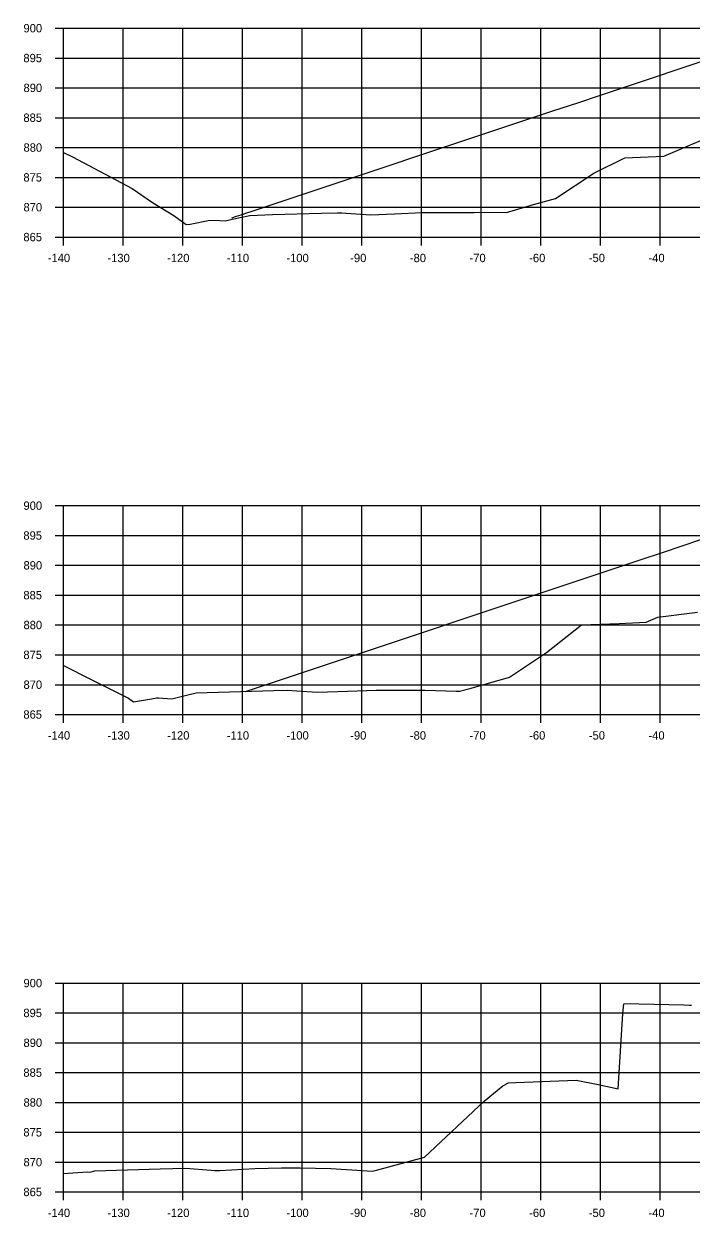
# Model space of a CAD drawing. Extents: x 1098669 to 1198896, y 698679 to 704410.
# Drawn here: x 1113352.2 to 1113464.1, y 701994.3 to 702194.3 of the extents above; entities that cross this region are included whole.
import ezdxf

# ---------------------------------------------------------------- set-up
doc = ezdxf.new("R2010")
doc.units = 0
for name, color, linetype in [('R_Alt Surface', 7, 'Continuous'), ('R_Axis', 7, 'Continuous'), ('R_Axis Annot', 7, 'Continuous'), ('R_Fin Surface', 7, 'Continuous'), ('R_Grid', 7, 'Continuous')]:
    doc.layers.add(name, color=color, linetype=linetype)

msp = doc.modelspace()

# ---------------------------------------------------------------- linework, layer by layer
at = {"layer": 'R_Alt Surface'}
for points in [[(1113358.87, 702172.72), (1113360.36, 702171.98), (1113370.35, 702166.7), (1113373.79, 702164.37), (1113377.36, 702162.16), (1113379.43, 702160.64), (1113380.09, 702160.75), (1113383.37, 702161.41), (1113385.07, 702161.33), (1113385.98, 702161.28), (1113387.14, 702161.57), (1113390.09, 702162.2), (1113393.86, 702162.32), (1113402.08, 702162.55), (1113404.77, 702162.63), (1113405.48, 702162.64), (1113406.2, 702162.59), (1113410.35, 702162.29), (1113414.32, 702162.44), (1113419, 702162.7), (1113422.09, 702162.69), (1113425.76, 702162.68), (1113427.67, 702162.68), (1113428.77, 702162.73), (1113433.12, 702162.68), (1113437.65, 702163.99), (1113441.3, 702165.02), (1113447.73, 702169.29), (1113452.93, 702171.81), (1113459.47, 702172.09), (1113465.81, 702174.79)], [(1113358.87, 702086.76), (1113363.51, 702084.43), (1113369.72, 702081.31), (1113370.59, 702080.67), (1113373.91, 702081.23), (1113374.46, 702081.34), (1113374.75, 702081.33), (1113377.03, 702081.21), (1113379.94, 702081.93), (1113381.06, 702082.17), (1113394.08, 702082.57), (1113396.35, 702082.63), (1113397.94, 702082.52), (1113401.35, 702082.3), (1113404.84, 702082.39), (1113411.26, 702082.66), (1113411.4, 702082.66), (1113419.49, 702082.62), (1113424.66, 702082.49), (1113425.22, 702082.45), (1113427.21, 702083), (1113433.62, 702084.8), (1113439.83, 702088.93), (1113445.7, 702093.57), (1113452.02, 702093.83), (1113456.54, 702094.02), (1113458.5, 702094.86), (1113465.11, 702095.69)], [(1113358.87, 702001.68), (1113362.84, 702001.94), (1113363.25, 702001.9), (1113364.08, 702002.1), (1113375.06, 702002.44), (1113379.29, 702002.57), (1113383.62, 702002.19), (1113384.18, 702002.13), (1113385.03, 702002.18), (1113390.92, 702002.48), (1113395.4, 702002.6), (1113398.51, 702002.59), (1113403.68, 702002.52), (1113408.93, 702002.14), (1113410.59, 702002.03), (1113411.34, 702002.23), (1113419.39, 702004.41), (1113429.36, 702013.77), (1113432.47, 702016.36), (1113433.42, 702016.83), (1113434.66, 702016.91), (1113444.78, 702017.28), (1113448.46, 702016.56), (1113451.84, 702015.83), (1113452.59, 702028.48), (1113452.8, 702030.1), (1113453.94, 702030.13), (1113455.28, 702030.1), (1113462.83, 702029.94), (1113463.79, 702029.84), (1113464.1, 702029.84)]]:
    msp.add_lwpolyline(points, dxfattribs=at)
at = {"layer": 'R_Axis'}
for p, q in [((1113357.47, 702193.56), (1113358.87, 702193.56)), ((1113358.87, 702158.56), (1113358.87, 702193.56)), ((1113357.47, 702188.56), (1113358.87, 702188.56)), ((1113357.47, 702183.56), (1113358.87, 702183.56)), ((1113357.47, 702178.56), (1113358.87, 702178.56)), ((1113357.47, 702173.56), (1113358.87, 702173.56)), ((1113357.47, 702168.56), (1113358.87, 702168.56)), ((1113357.47, 702163.56), (1113358.87, 702163.56)), ((1113357.47, 702158.56), (1113358.87, 702158.56)), ((1113358.87, 702158.56), (1113638.87, 702158.56)), ((1113358.87, 702157.16), (1113358.87, 702158.56)), ((1113368.87, 702157.16), (1113368.87, 702158.56)), ((1113378.87, 702157.16), (1113378.87, 702158.56)), ((1113388.87, 702157.16), (1113388.87, 702158.56)), ((1113398.87, 702157.16), (1113398.87, 702158.56)), ((1113408.87, 702157.16), (1113408.87, 702158.56)), ((1113418.87, 702157.16), (1113418.87, 702158.56)), ((1113428.87, 702157.16), (1113428.87, 702158.56)), ((1113438.87, 702157.16), (1113438.87, 702158.56)), ((1113448.87, 702157.16), (1113448.87, 702158.56)), ((1113458.87, 702157.16), (1113458.87, 702158.56)), ((1113357.47, 702113.56), (1113358.87, 702113.56)), ((1113358.87, 702078.56), (1113358.87, 702113.56)), ((1113357.47, 702108.56), (1113358.87, 702108.56)), ((1113357.47, 702103.56), (1113358.87, 702103.56)), ((1113357.47, 702098.56), (1113358.87, 702098.56)), ((1113357.47, 702093.56), (1113358.87, 702093.56)), ((1113357.47, 702088.56), (1113358.87, 702088.56)), ((1113357.47, 702083.56), (1113358.87, 702083.56)), ((1113357.47, 702078.56), (1113358.87, 702078.56)), ((1113358.87, 702078.56), (1113638.87, 702078.56)), ((1113358.87, 702077.16), (1113358.87, 702078.56)), ((1113368.87, 702077.16), (1113368.87, 702078.56)), ((1113378.87, 702077.16), (1113378.87, 702078.56)), ((1113388.87, 702077.16), (1113388.87, 702078.56)), ((1113398.87, 702077.16), (1113398.87, 702078.56)), ((1113408.87, 702077.16), (1113408.87, 702078.56)), ((1113418.87, 702077.16), (1113418.87, 702078.56)), ((1113428.87, 702077.16), (1113428.87, 702078.56)), ((1113438.87, 702077.16), (1113438.87, 702078.56)), ((1113448.87, 702077.16), (1113448.87, 702078.56)), ((1113458.87, 702077.16), (1113458.87, 702078.56)), ((1113357.47, 702033.56), (1113358.87, 702033.56)), ((1113358.87, 701998.56), (1113358.87, 702033.56)), ((1113357.47, 702028.56), (1113358.87, 702028.56)), ((1113357.47, 702023.56), (1113358.87, 702023.56)), ((1113357.47, 702018.56), (1113358.87, 702018.56)), ((1113357.47, 702013.56), (1113358.87, 702013.56)), ((1113357.47, 702008.56), (1113358.87, 702008.56)), ((1113357.47, 702003.56), (1113358.87, 702003.56)), ((1113357.47, 701998.56), (1113358.87, 701998.56)), ((1113358.87, 701998.56), (1113638.87, 701998.56)), ((1113358.87, 701997.16), (1113358.87, 701998.56)), ((1113368.87, 701997.16), (1113368.87, 701998.56)), ((1113378.87, 701997.16), (1113378.87, 701998.56)), ((1113388.87, 701997.16), (1113388.87, 701998.56)), ((1113398.87, 701997.16), (1113398.87, 701998.56)), ((1113408.87, 701997.16), (1113408.87, 701998.56)), ((1113418.87, 701997.16), (1113418.87, 701998.56)), ((1113428.87, 701997.16), (1113428.87, 701998.56)), ((1113438.87, 701997.16), (1113438.87, 701998.56)), ((1113448.87, 701997.16), (1113448.87, 701998.56)), ((1113458.87, 701997.16), (1113458.87, 701998.56))]:
    msp.add_line(p, q, dxfattribs=at)
at = {"layer": 'R_Fin Surface'}
for points in [[(1113387.06, 702161.77), (1113387.86, 702162.04), (1113388.65, 702162.3), (1113389.02, 702162.42), (1113389.27, 702162.5), (1113390.8, 702163), (1113440.89, 702179.69), (1113445.22, 702181.13), (1113448.51, 702182.23), (1113471.13, 702189.78)], [(1113389.33, 702082.42), (1113456.55, 702104.82), (1113458.27, 702105.39), (1113459.57, 702105.82), (1113468.51, 702108.81), (1113468.94, 702108.95), (1113469.65, 702109.19), (1113471.08, 702109.67), (1113475.37, 702111.1), (1113480.37, 702111), (1113483.37, 702110.94), (1113483.87, 702110.94), (1113484.87, 702110.46), (1113498.87, 702110.74), (1113512.87, 702110.46), (1113513.87, 702110.94), (1113514.37, 702110.94), (1113517.37, 702111), (1113522.37, 702111.1), (1113582.64, 702091.01), (1113598.79, 702096.4)]]:
    msp.add_lwpolyline(points, dxfattribs=at)
at = {"layer": 'R_Grid'}
for p, q in [((1113358.87, 702193.56), (1113638.87, 702193.56)), ((1113358.87, 702158.56), (1113358.87, 702193.56)), ((1113368.87, 702158.56), (1113368.87, 702193.56)), ((1113378.87, 702158.56), (1113378.87, 702193.56)), ((1113388.87, 702158.56), (1113388.87, 702193.56)), ((1113398.87, 702158.56), (1113398.87, 702193.56)), ((1113408.87, 702158.56), (1113408.87, 702193.56)), ((1113418.87, 702158.56), (1113418.87, 702193.56)), ((1113428.87, 702158.56), (1113428.87, 702193.56)), ((1113438.87, 702158.56), (1113438.87, 702193.56)), ((1113448.87, 702158.56), (1113448.87, 702193.56)), ((1113458.87, 702158.56), (1113458.87, 702193.56)), ((1113358.87, 702188.56), (1113638.87, 702188.56)), ((1113358.87, 702183.56), (1113638.87, 702183.56)), ((1113358.87, 702178.56), (1113638.87, 702178.56)), ((1113358.87, 702173.56), (1113638.87, 702173.56)), ((1113358.87, 702168.56), (1113638.87, 702168.56)), ((1113358.87, 702163.56), (1113638.87, 702163.56)), ((1113358.87, 702158.56), (1113638.87, 702158.56)), ((1113358.87, 702113.56), (1113638.87, 702113.56)), ((1113358.87, 702078.56), (1113358.87, 702113.56)), ((1113368.87, 702078.56), (1113368.87, 702113.56)), ((1113378.87, 702078.56), (1113378.87, 702113.56)), ((1113388.87, 702078.56), (1113388.87, 702113.56)), ((1113398.87, 702078.56), (1113398.87, 702113.56)), ((1113408.87, 702078.56), (1113408.87, 702113.56)), ((1113418.87, 702078.56), (1113418.87, 702113.56)), ((1113428.87, 702078.56), (1113428.87, 702113.56)), ((1113438.87, 702078.56), (1113438.87, 702113.56)), ((1113448.87, 702078.56), (1113448.87, 702113.56)), ((1113458.87, 702078.56), (1113458.87, 702113.56)), ((1113358.87, 702108.56), (1113638.87, 702108.56)), ((1113358.87, 702103.56), (1113638.87, 702103.56)), ((1113358.87, 702098.56), (1113638.87, 702098.56)), ((1113358.87, 702093.56), (1113638.87, 702093.56)), ((1113358.87, 702088.56), (1113638.87, 702088.56)), ((1113358.87, 702083.56), (1113638.87, 702083.56)), ((1113358.87, 702078.56), (1113638.87, 702078.56)), ((1113358.87, 702033.56), (1113638.87, 702033.56)), ((1113358.87, 701998.56), (1113358.87, 702033.56)), ((1113368.87, 701998.56), (1113368.87, 702033.56)), ((1113378.87, 701998.56), (1113378.87, 702033.56)), ((1113388.87, 701998.56), (1113388.87, 702033.56)), ((1113398.87, 701998.56), (1113398.87, 702033.56)), ((1113408.87, 701998.56), (1113408.87, 702033.56)), ((1113418.87, 701998.56), (1113418.87, 702033.56)), ((1113428.87, 701998.56), (1113428.87, 702033.56)), ((1113438.87, 701998.56), (1113438.87, 702033.56)), ((1113448.87, 701998.56), (1113448.87, 702033.56)), ((1113458.87, 701998.56), (1113458.87, 702033.56)), ((1113358.87, 702028.56), (1113638.87, 702028.56)), ((1113358.87, 702023.56), (1113638.87, 702023.56)), ((1113358.87, 702018.56), (1113638.87, 702018.56)), ((1113358.87, 702013.56), (1113638.87, 702013.56)), ((1113358.87, 702008.56), (1113638.87, 702008.56)), ((1113358.87, 702003.56), (1113638.87, 702003.56)), ((1113358.87, 701998.56), (1113638.87, 701998.56))]:
    msp.add_line(p, q, dxfattribs=at)

# ---------------------------------------------------------------- texts
at = {"layer": 'R_Axis Annot'}
for s, p in [('900', (1113352.14, 702192.86)), ('895', (1113352.12, 702187.86)), ('890', (1113352.14, 702182.86)), ('885', (1113352.12, 702177.86)), ('880', (1113352.14, 702172.86)), ('875', (1113352.12, 702167.86)), ('870', (1113352.14, 702162.86)), ('865', (1113352.12, 702157.86)), ('-140', (1113356.21, 702154.36)), ('-130', (1113366.21, 702154.36)), ('-120', (1113376.21, 702154.36)), ('-110', (1113386.21, 702154.36)), ('-100', (1113396.21, 702154.36)), ('-90', (1113406.91, 702154.36)), ('-80', (1113416.91, 702154.36)), ('-70', (1113426.91, 702154.36)), ('-60', (1113436.91, 702154.36)), ('-50', (1113446.91, 702154.36)), ('-40', (1113456.91, 702154.36)), ('900', (1113352.14, 702112.86)), ('895', (1113352.12, 702107.86)), ('890', (1113352.14, 702102.86)), ('885', (1113352.12, 702097.86)), ('880', (1113352.14, 702092.86)), ('875', (1113352.12, 702087.86)), ('870', (1113352.14, 702082.86)), ('865', (1113352.12, 702077.86)), ('-140', (1113356.21, 702074.36)), ('-130', (1113366.21, 702074.36)), ('-120', (1113376.21, 702074.36)), ('-110', (1113386.21, 702074.36)), ('-100', (1113396.21, 702074.36)), ('-90', (1113406.91, 702074.36)), ('-80', (1113416.91, 702074.36)), ('-70', (1113426.91, 702074.36)), ('-60', (1113436.91, 702074.36)), ('-50', (1113446.91, 702074.36)), ('-40', (1113456.91, 702074.36)), ('900', (1113352.14, 702032.86)), ('895', (1113352.12, 702027.86)), ('890', (1113352.14, 702022.86)), ('885', (1113352.12, 702017.86)), ('880', (1113352.14, 702012.86)), ('875', (1113352.12, 702007.86)), ('870', (1113352.14, 702002.86)), ('865', (1113352.12, 701997.86)), ('-140', (1113356.21, 701994.36)), ('-130', (1113366.21, 701994.36)), ('-120', (1113376.21, 701994.36)), ('-110', (1113386.21, 701994.36)), ('-100', (1113396.21, 701994.36)), ('-90', (1113406.91, 701994.36)), ('-80', (1113416.91, 701994.36)), ('-70', (1113426.91, 701994.36)), ('-60', (1113436.91, 701994.36)), ('-50', (1113446.91, 701994.36)), ('-40', (1113456.91, 701994.36))]:
    msp.add_text(s, height=1.4, dxfattribs=at).set_placement(p)

doc.saveas('drawing.dxf')
